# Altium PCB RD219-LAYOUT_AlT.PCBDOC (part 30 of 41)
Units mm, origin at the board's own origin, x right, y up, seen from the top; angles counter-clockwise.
Board outline 209.75 x 159.97 mm, 2 copper layers (TOP, BOTTOM), stack 0 mm thick; 398 components, 199 nets, 1469 pads, 0 vias.
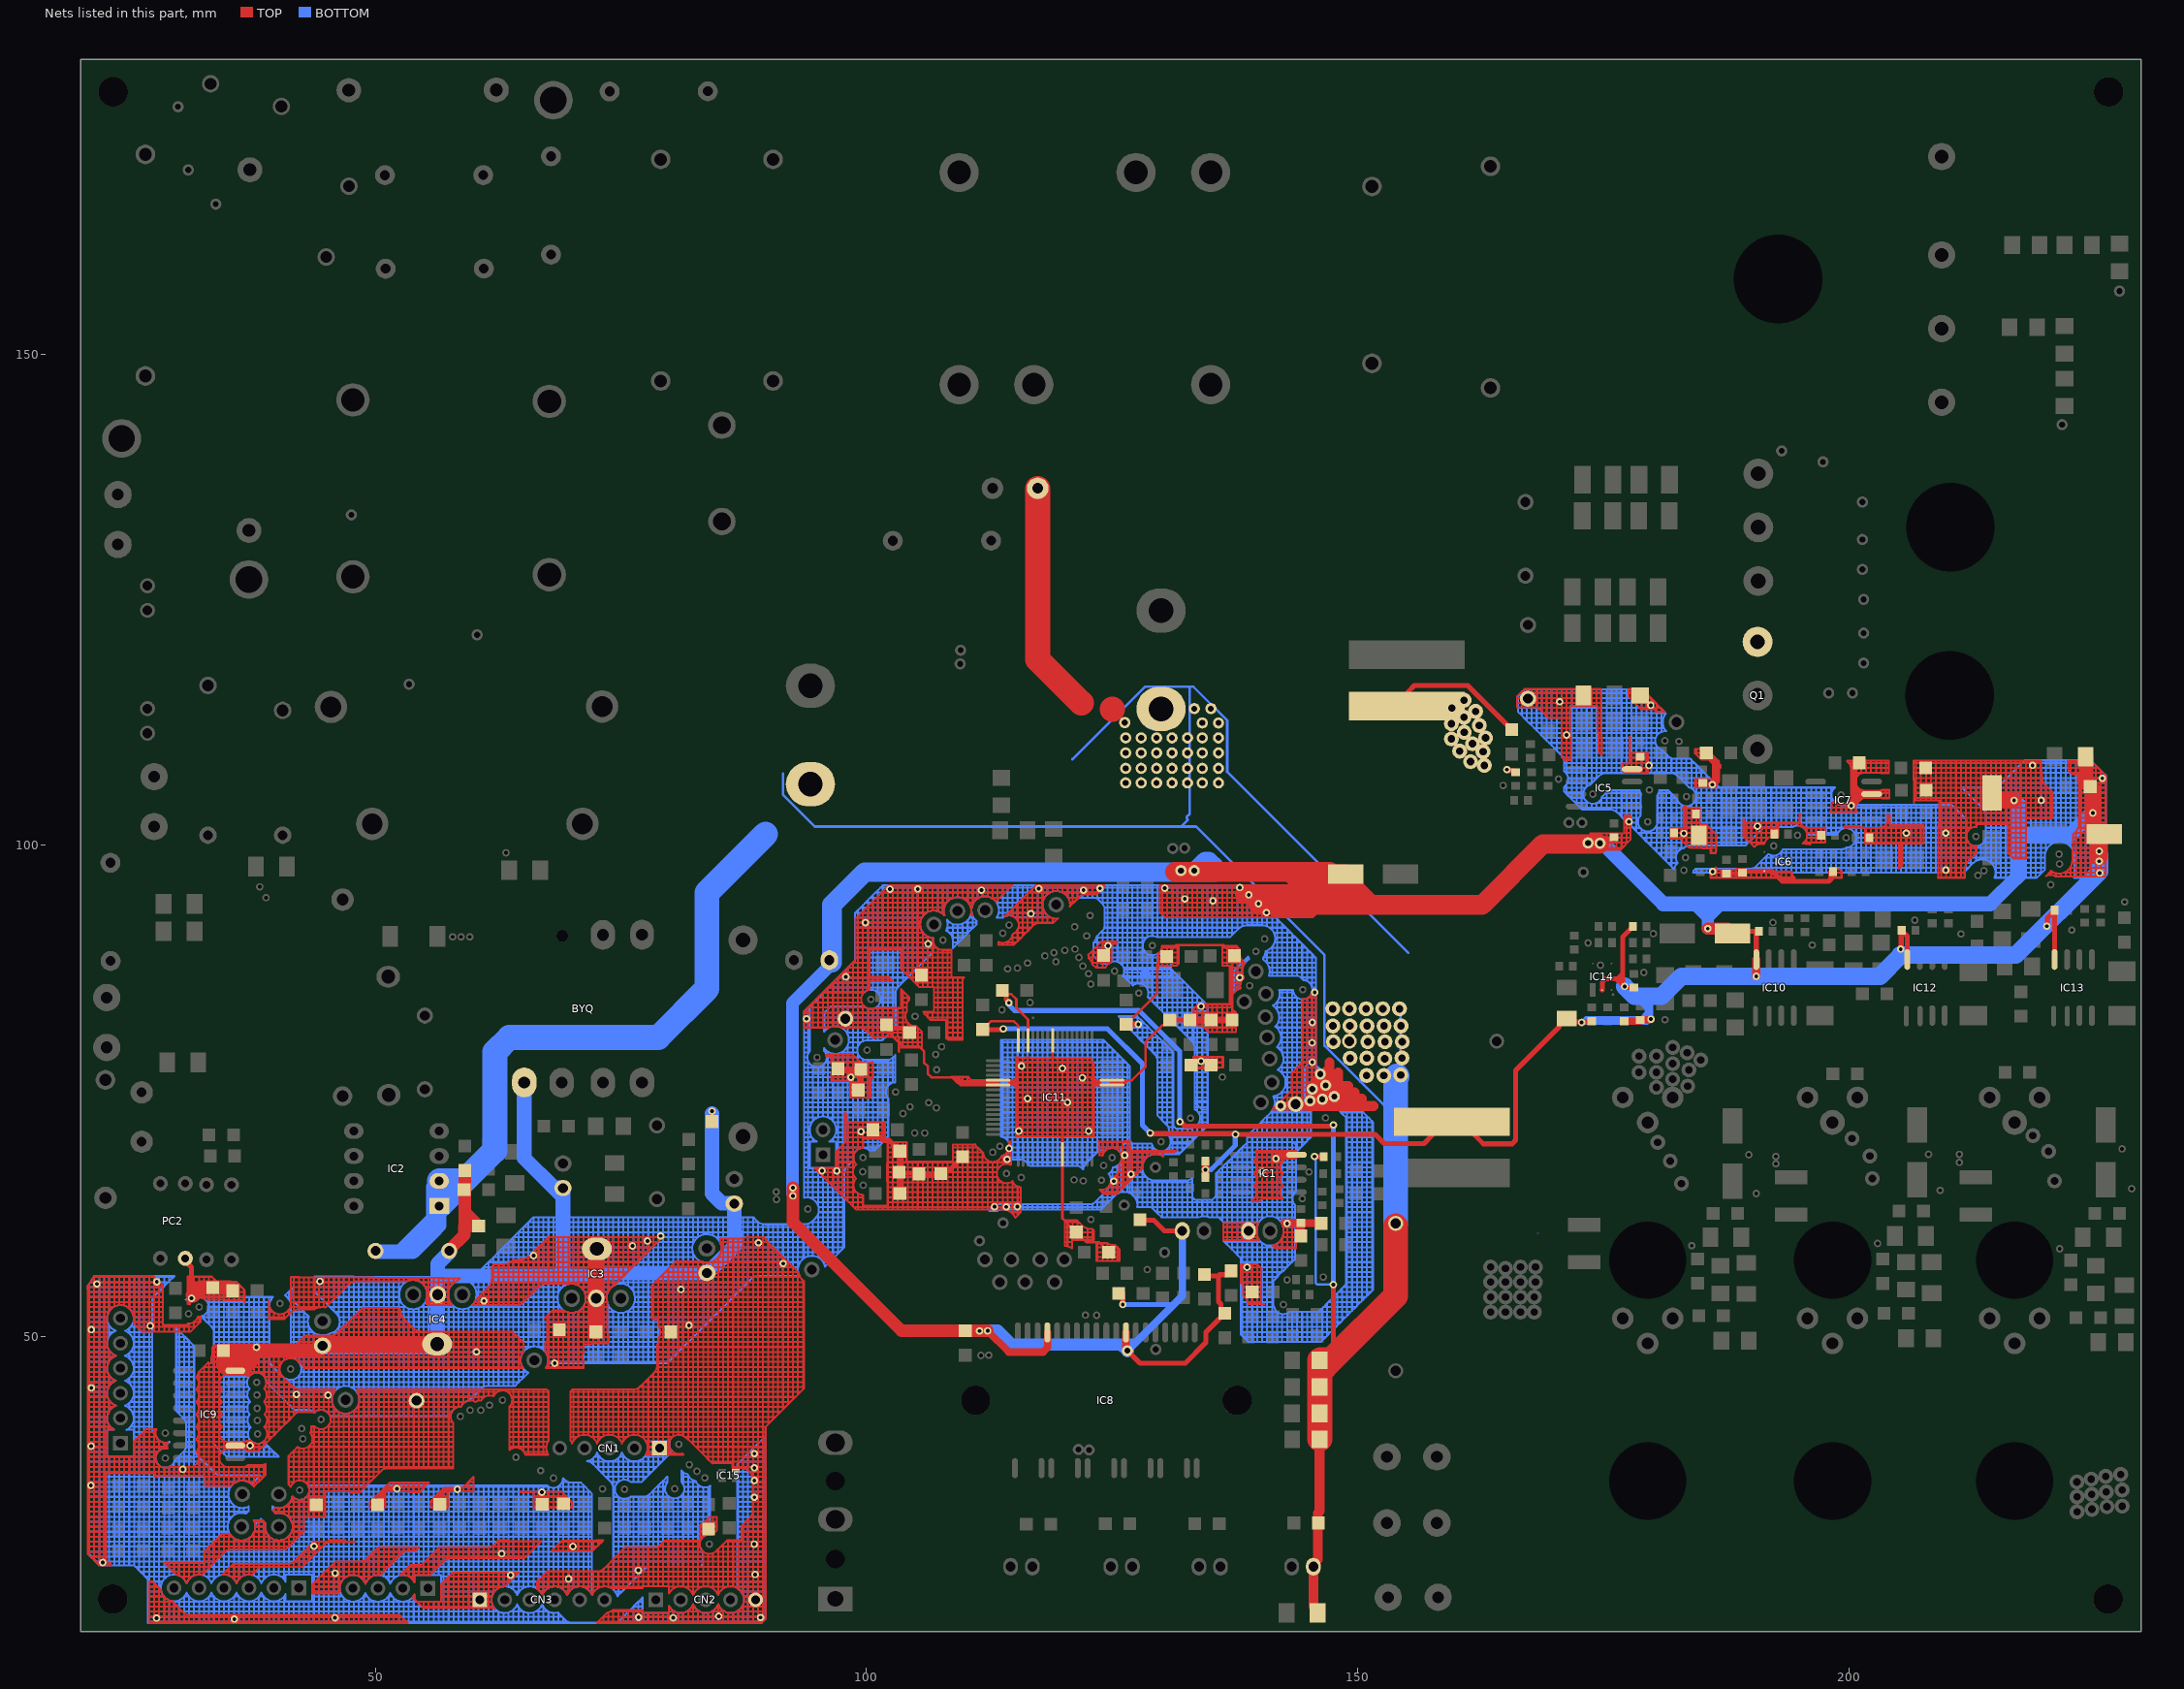
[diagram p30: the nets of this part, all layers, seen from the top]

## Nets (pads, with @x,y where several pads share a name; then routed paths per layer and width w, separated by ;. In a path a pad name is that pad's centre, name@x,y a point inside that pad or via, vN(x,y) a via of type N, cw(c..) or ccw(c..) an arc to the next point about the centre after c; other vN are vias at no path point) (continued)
GND: (continued)
  BOTTOM w0.203: 98.613,86.548 99.121,86.548 ; 98.613,87.056 98.613,87.564 ; 98.613,87.056 99.121,87.056 ; 98.613,87.564 98.613,88.072 ; 98.613,87.564 99.121,87.564 ; 98.613,88.072 98.81,88.269 98.81,88.58 ; 98.613,88.072 99.121,88.072 ; 98.81,88.58 98.81,89.088 ; 98.81,88.58 99.121,88.58 ; 98.81,89.088 98.81,89.596 ; 98.81,89.088 99.121,89.088 ; 98.81,89.596 99.121,89.596 ; 98.81,89.596 98.81,90.104 ; 98.81,90.104 99.121,90.104 ; 98.81,90.104 98.81,90.612 ; 98.81,90.612 99.121,90.612 ; 98.81,90.612 98.81,91.12 ; 98.81,91.12 99.121,91.12 ; 98.81,91.12 98.81,91.628 ; 98.81,91.628 99.121,91.628 ; 98.81,91.628 98.81,92.136 ; 98.81,92.136 99.121,92.136 ; 98.81,92.136 98.81,92.644 ; 98.81,92.644 99.121,92.644 ; 98.81,92.644 98.81,93.095 99.121,93.406 ; 98.816,68.768 cw(c99.642,68.236) 98.818,68.771 cw(c99.642,68.236) 99.121,69.069 ; 99.078,78.928 ccw(c100.051,79.165) 99.121,78.792 ; 99.078,78.928 cw(c100.051,79.165) 99.086,79.436 ; 99.086,79.436 cw(c100.051,79.165) 99.121,79.538 ; 99.121,69.069 cw(c99.642,68.236) 99.629,69.218 ; 99.121,69.069 99.121,69.276 ; 99.121,69.276 99.629,69.276 ; 99.121,69.276 99.121,69.784 ; 99.121,69.784 99.121,70.292 ; 99.121,69.784 99.629,69.784 ; 99.121,70.292 pad.@99.121,70.8 ; 99.121,70.292 99.629,70.292 ; pad.@99.121,70.8 99.121,71.308 ; pad.@99.121,70.8 pad.@99.629,70.8 ; 99.121,71.308 99.121,71.816 ; 99.121,71.308 99.629,71.308 ; 99.121,71.816 99.121,72.324 ; 99.121,71.816 99.629,71.816 ; 99.121,72.324 99.121,72.832 ; 99.121,72.324 99.629,72.324 ; 99.121,72.832 99.121,73.34 ; 99.121,72.832 99.629,72.832 ; 99.121,73.34 99.121,73.848 ; 99.121,73.34 99.629,73.34 ; 99.121,73.848 99.121,74.356 ; 99.121,73.848 99.629,73.848 ; 99.121,74.356 99.121,74.864 ; 99.121,74.356 99.629,74.356 ; 99.121,74.864 99.121,75.372 ; 99.121,74.864 99.629,74.864 ; 99.121,75.372 99.121,75.88 ; 99.121,75.372 99.629,75.372 ; 99.121,75.88 99.121,76.388 ; 99.121,75.88 99.629,75.88 ; 99.121,76.388 99.121,76.896 ; 99.121,76.388 99.629,76.388 ; 99.121,76.896 99.121,77.404 ; 99.121,76.896 99.629,76.896 ; 99.121,77.404 99.121,77.912 ; 99.121,77.404 99.629,77.404 ; 99.121,77.912 99.121,78.42 ; 99.121,77.912 99.629,77.912 ; 99.121,78.42 99.381,78.42 ; 99.121,78.42 99.121,78.792 ; 99.121,78.792 ccw(c100.051,79.165) 99.122,78.79 ccw(c100.051,79.165) 99.381,78.42 ; 99.121,79.538 cw(c100.051,79.165) 99.122,79.54 cw(c100.051,79.165) 99.42,79.944 ; 99.121,79.538 99.121,79.944 ; 99.121,79.944 99.121,80.452 ; 99.121,79.944 99.421,79.944 ; 99.121,80.452 99.121,80.96 ; 99.121,80.452 99.629,80.452 ; 99.121,80.96 99.121,81.468 ; 99.121,80.96 99.629,80.96 ; 99.121,81.468 99.629,81.468 ; 99.121,81.468 99.121,81.976 ; 99.121,81.976 99.121,82.484 ; 99.121,81.976 99.629,81.976 ; 99.121,82.484 99.121,82.992 ; 99.121,82.484 99.629,82.484 ; 99.121,82.992 99.629,82.992 ; 99.121,82.992 99.121,83.5 ; 99.121,83.5 99.629,83.5 ; 99.121,83.5 99.121,83.605 ; 99.121,83.605 99.629,83.605 ; 99.121,85.062 99.629,85.062 ; 99.121,85.062 99.121,85.532 ; 99.121,85.532 99.629,85.532 ; 99.121,85.532 99.121,86.04 ; 99.121,86.04 99.121,86.548 ; 99.121,86.04 99.629,86.04 ; 99.121,86.548 99.121,87.056 ; 99.121,86.548 99.629,86.548 ; 99.121,87.056 99.121,87.564 ; 99.121,87.056 99.629,87.056 ; 99.121,87.564 99.121,88.072 ; 99.121,87.564 99.629,87.564 ; 99.121,88.072 99.121,88.58 ; 99.121,88.072 99.629,88.072 ; 99.121,88.58 99.121,89.088 ; 99.121,88.58 99.629,88.58 ; 99.121,89.088 99.629,89.088 ; 99.121,89.088 99.121,89.596 ; 99.121,89.596 99.121,90.104 ; 99.121,89.596 99.629,89.596 ; 99.121,90.104 99.121,90.612 ; 99.121,90.104 99.629,90.104 ; 99.121,90.612 99.121,91.12 ; 99.121,90.612 99.629,90.612 ; 99.121,91.12 99.121,91.628 ; 99.121,91.12 99.629,91.12 ; 99.121,91.628 99.121,92.136 ; 99.121,91.628 99.629,91.628 ; 99.121,92.136 99.121,92.644 ; 99.121,92.136 pad.@99.629,92.136 ; 99.121,92.644 99.121,93.152 ; 99.121,92.644 99.629,92.644 ; 99.121,93.152 99.629,93.152 ; 99.121,93.152 99.121,93.406 ; 99.121,93.406 99.375,93.66 ; 99.375,93.66 99.629,93.914 ; 99.375,93.66 99.629,93.66 ; 99.381,78.42 ccw(c100.051,79.165) 99.627,78.257 ccw(c100.051,79.165) 99.629,78.257 ; 99.421,79.944 cw(c100.051,79.165) 99.629,80.074 ; 99.629,69.218 cw(c99.642,68.236) 99.642,69.219 cw(c99.642,68.236) 100.137,69.085 ; 99.629,69.218 99.629,69.276 ; 99.629,69.276 99.629,69.784 ; 99.629,69.276 100.137,69.276 ; 99.629,69.784 100.137,69.784 ; 99.629,69.784 99.629,70.292 ; 99.629,70.292 100.137,70.292 ; 99.629,70.292 pad.@99.629,70.8 ; pad.@99.629,70.8 100.137,70.8 ; pad.@99.629,70.8 99.629,71.308 ; 99.629,71.308 99.629,71.816 ; 99.629,71.308 100.137,71.308 ; 99.629,71.816 99.629,72.324 ; 99.629,71.816 100.137,71.816 ; 99.629,72.324 100.137,72.324 ; 99.629,72.324 99.629,72.832 ; 99.629,72.832 99.629,73.34 ; 99.629,72.832 100.137,72.832 ; 99.629,73.34 99.629,73.848 ; 99.629,73.34 100.137,73.34 ; 99.629,73.848 99.629,74.356 ; 99.629,73.848 100.137,73.848 ; 99.629,74.356 100.137,74.356 ; 99.629,74.356 99.629,74.864 ; 99.629,74.864 99.629,75.372 ; 99.629,74.864 100.137,74.864 ; 99.629,75.372 100.137,75.372 ; 99.629,75.372 99.629,75.88 ; 99.629,75.88 100.137,75.88 ; 99.629,75.88 99.629,76.388 ; 99.629,76.388 99.629,76.896 ; 99.629,76.388 100.137,76.388 ; 99.629,76.896 99.629,77.404 ; 99.629,76.896 100.137,76.896 ; 99.629,77.404 99.629,77.912 ; 99.629,77.404 100.137,77.404 ; 99.629,77.912 100.137,77.912 ; 99.629,77.912 99.629,78.257 ; 99.629,78.257 ccw(c100.051,79.165) 100.051,78.164 100.137,78.164 ; 99.629,80.074 cw(c100.051,79.165) 100.051,80.167 100.137,80.167 ; 99.629,80.074 99.629,80.452 ; 99.629,80.452 99.629,80.96 ; 99.629,80.452 100.137,80.452 ; 99.629,80.96 99.629,81.468 ; 99.629,80.96 100.137,80.96 ; 99.629,81.468 100.137,81.468 ; 99.629,81.468 99.629,81.976 ; 99.629,81.976 99.629,82.484 ; 99.629,81.976 100.137,81.976 ; 99.629,82.484 99.629,82.992 ; 99.629,82.484 100.137,82.484 ; 99.629,82.992 99.629,83.5 ; 99.629,82.992 100.137,82.992 ; 99.629,83.5 99.629,83.605 ; 99.629,83.5 99.924,83.5 ; 99.629,85.062 99.629,85.532 ; 99.629,85.532 100.137,85.532 ; 99.629,85.532 99.629,86.04 ; 99.629,86.04 99.629,86.548 ; 99.629,86.04 100.137,86.04 ; 99.629,86.548 99.629,87.056 ; 99.629,86.548 100.137,86.548 ; 99.629,87.056 99.629,87.564 ; 99.629,87.056 100.137,87.056 ; 99.629,87.564 99.629,88.072 ; 99.629,87.564 100.137,87.564 ; 99.629,88.072 99.629,88.58 ; 99.629,88.072 100.137,88.072 ; 99.629,88.58 99.629,89.088 ; 99.629,88.58 100.137,88.58 ; 99.629,89.088 100.137,89.088 ; 99.629,89.088 99.629,89.596 ; 99.629,89.596 99.629,90.104 ; 99.629,89.596 100.137,89.596 ; 99.629,90.104 99.629,90.612 ; 99.629,90.104 100.137,90.104 ; 99.629,90.612 99.629,91.12 ; 99.629,90.612 100.137,90.612 ; 99.629,91.12 99.629,91.628 ; 99.629,91.12 100.137,91.12 ; 99.629,91.628 100.137,91.628 ; 99.629,91.628 pad.@99.629,92.136 ; pad.@99.629,92.136 pad.@99.883,92.136 pad.@100.137,92.136 ; pad.@99.629,92.136 99.629,92.644 ; 99.629,92.644 99.629,93.152 ; 99.629,92.644 100.137,92.644 ; 99.629,93.152 100.137,93.152 ; 99.629,93.152 99.629,93.66 ; 99.629,93.66 99.629,93.914 ; 99.629,93.66 100.137,93.66 ; 99.629,93.914 99.883,94.168 ; 99.883,94.168 100.137,94.168 ; 99.883,94.168 100.137,94.422 ; 99.924,83.5 ccw(c100.444,84.334) 100.137,83.4 ; 100.137,69.085 100.137,69.276 ; 100.137,69.276 100.137,69.784 ; 100.137,69.276 100.645,69.276 ; 100.137,69.784 100.645,69.784 ; 100.137,69.784 100.137,70.292 ; 100.137,70.292 100.645,70.292 ; 100.137,70.292 100.137,70.8 ; 100.137,70.8 100.137,71.308 ; 100.137,70.8 100.645,70.8 ; 100.137,71.308 100.137,71.816 ; 100.137,71.308 100.645,71.308 ; 100.137,71.816 100.137,72.324 ; 100.137,71.816 100.645,71.816 ; 100.137,72.324 100.645,72.324 ; 100.137,72.324 100.137,72.832 ; 100.137,72.832 100.137,73.34 ; 100.137,72.832 100.645,72.832 ; 100.137,73.34 100.137,73.848 ; 100.137,73.34 100.645,73.34 ; 100.137,73.848 100.137,74.356 ; 100.137,73.848 100.645,73.848 ; 100.137,74.356 100.645,74.356 ; 100.137,74.356 100.137,74.864 ; 100.137,74.864 100.137,75.372 ; 100.137,74.864 100.645,74.864 ; 100.137,75.372 100.645,75.372 ; 100.137,75.372 100.137,75.88 ; 100.137,75.88 100.645,75.88 ; 100.137,75.88 100.137,76.388 ; 100.137,76.388 100.137,76.896 ; 100.137,76.388 100.645,76.388 ; 100.137,76.896 100.137,77.404 ; 100.137,76.896 100.645,76.896 ; 100.137,77.404 100.137,77.912 ; 100.137,77.404 100.645,77.404 ; 100.137,77.912 100.137,78.164 ; 100.137,77.912 100.645,77.912 ; 100.137,78.164 100.645,78.164 ; 100.137,80.167 100.645,80.167 ; 100.137,80.167 100.137,80.452 ; 100.137,80.452 100.137,80.96 ; 100.137,80.452 100.645,80.452 ; 100.137,80.96 100.137,81.468 ; 100.137,80.96 100.645,80.96 ; 100.137,81.468 100.645,81.468 ; 100.137,81.468 100.137,81.976 ; 100.137,81.976 100.137,82.484 ; 100.137,81.976 100.645,81.976 ; 100.137,82.484 100.137,82.992 ; 100.137,82.484 100.645,82.484 ; 100.137,82.992 100.645,82.992 ; 100.137,82.992 100.137,83.4 ; 100.137,83.4 ccw(c100.444,84.334) 100.645,83.372 ; 100.137,85.267 cw(c100.444,84.334) 100.14,85.268 cw(c100.444,84.334) 100.645,85.296 ; 100.137,85.267 100.137,85.532 ; 100.137,85.532 100.137,86.04 ; 100.137,85.532 100.645,85.532 ; 100.137,86.04 100.137,86.548 ; 100.137,86.04 100.645,86.04 ; 100.137,86.548 100.137,87.056 ; 100.137,86.548 100.645,86.548 ; 100.137,87.056 100.137,87.564 ; 100.137,87.056 100.645,87.056 ; 100.137,87.564 100.137,88.072 ; 100.137,87.564 100.645,87.564 ; 100.137,88.072 100.137,88.58 ; 100.137,88.072 100.645,88.072 ; 100.137,88.58 100.137,89.088 ; 100.137,88.58 100.645,88.58 ; 100.137,89.088 100.137,89.596 ; 100.137,89.088 100.645,89.088 ; 100.137,89.596 100.137,90.104 ; 100.137,89.596 100.645,89.596 ; 100.137,90.104 100.137,90.612 ; 100.137,90.104 100.645,90.104 ; 100.137,90.612 100.137,91.12 ; 100.137,90.612 100.645,90.612 ; 100.137,91.12 100.137,91.628 ; 100.137,91.12 100.645,91.12 ; 100.137,91.628 100.645,91.628 ; 100.137,91.628 pad.@100.137,92.136 ; pad.@100.137,92.136 100.645,92.136 ; pad.@100.137,92.136 100.137,92.644 ; 100.137,92.644 100.137,93.152 ; 100.137,92.644 100.645,92.644 ; 100.137,93.152 100.137,93.66 ; 100.137,93.152 100.645,93.152 ; 100.137,93.66 100.137,94.168 ; 100.137,93.66 100.645,93.66 ; 100.137,94.168 100.137,94.422 ; 100.137,94.168 100.645,94.168 ; 100.137,94.422 100.391,94.676 ; 100.391,94.676 100.645,94.676 ; 100.391,94.676 100.645,94.93 ; 100.645,68.965 100.827,68.965 101.139,69.276 ; 100.645,68.965 100.645,69.276 ; 100.645,69.276 100.645,69.784 ; 100.645,69.276 101.139,69.276 ; 100.645,69.784 101.153,69.784 ; 100.645,69.784 100.645,70.292 ; 100.645,70.292 100.645,70.8 ; 100.645,70.292 101.153,70.292 ; 100.645,70.8 100.645,71.308 ; 100.645,70.8 101.153,70.8 ; 100.645,71.308 100.645,71.816 ; 100.645,71.308 101.153,71.308 ; 100.645,71.816 100.645,72.324 ; 100.645,71.816 101.153,71.816 ; 100.645,72.324 101.153,72.324 ; 100.645,72.324 100.645,72.832 ; 100.645,72.832 100.645,73.34 ; 100.645,72.832 101.153,72.832 ; 100.645,73.34 100.645,73.848 ; 100.645,73.34 101.153,73.34 ; 100.645,73.848 100.645,74.356 ; 100.645,73.848 101.153,73.848 ; 100.645,74.356 100.645,74.864 ; 100.645,74.356 101.153,74.356 ; 100.645,74.864 100.645,75.372 ; 100.645,74.864 101.153,74.864 ; 100.645,75.372 100.645,75.88 ; 100.645,75.372 101.153,75.372 ; 100.645,75.88 100.645,76.388 ; 100.645,75.88 101.153,75.88 ; 100.645,76.388 100.645,76.896 ; 100.645,76.388 101.153,76.388 ; 100.645,76.896 100.645,77.404 ; 100.645,76.896 101.153,76.896 ; 100.645,77.404 100.645,77.912 ; 100.645,77.404 101.153,77.404 ; 100.645,77.912 100.645,78.164 ; 100.645,77.912 101.153,77.912 ; 100.645,78.164 101.153,78.164 ; 100.645,80.167 100.645,80.452 ; 100.645,80.167 101.153,80.167 ; 100.645,80.452 100.645,80.96 ; 100.645,80.452 101.153,80.452 ; 100.645,80.96 100.645,81.468 ; 100.645,80.96 101.153,80.96 ; 100.645,81.468 100.645,81.976 ; 100.645,81.468 101.153,81.468 ; 100.645,81.976 100.645,82.484 ; 100.645,81.976 101.153,81.976 ; 100.645,82.484 100.645,82.992 ; 100.645,82.484 101.153,82.484 ; 100.645,82.992 101.153,82.992 ; 100.645,82.992 100.645,83.372 ; 100.645,83.372 ccw(c100.444,84.334) 100.648,83.373 ccw(c100.444,84.334) 100.963,83.5 101.153,83.5 ; 100.645,85.296 cw(c100.444,84.334) 100.648,85.295 cw(c100.444,84.334) 101.143,85.024 ; 100.645,85.296 100.645,85.532 ; 100.645,85.532 101.153,85.532 ; 100.645,85.532 100.645,86.04 ; 100.645,86.04 100.645,86.548 ; 100.645,86.04 101.153,86.04 ; 100.645,86.548 100.645,87.056 ; 100.645,86.548 101.153,86.548 ; 100.645,87.056 100.645,87.564 ; 100.645,87.056 101.153,87.056 ; 100.645,87.564 100.645,88.072 ; 100.645,87.564 101.153,87.564 ; 100.645,88.072 100.645,88.58 ; 100.645,88.072 101.153,88.072 ; 100.645,88.58 100.645,89.088 ; 100.645,88.58 101.153,88.58 ; 100.645,89.088 101.153,89.088 ; 100.645,89.088 100.645,89.596 ; 100.645,89.596 100.645,90.104 ; 100.645,89.596 101.153,89.596 ; 100.645,90.104 100.645,90.612 ; 100.645,90.104 101.153,90.104 ; 100.645,90.612 100.645,91.12 ; 100.645,90.612 101.153,90.612 ; 100.645,91.12 100.645,91.628 ; 100.645,91.12 101.153,91.12 ; 100.645,91.628 100.645,92.136 ; 100.645,91.628 101.153,91.628 ; 100.645,92.136 100.645,92.644 ; 100.645,92.136 101.153,92.136 ; 100.645,92.644 100.645,93.152 ; 100.645,92.644 101.153,92.644 ; 100.645,93.152 101.153,93.152 ; 100.645,93.152 100.645,93.66 ; 100.645,93.66 100.645,94.168 ; 100.645,93.66 101.153,93.66 ; 100.645,94.168 100.645,94.676 ; 100.645,94.168 101.153,94.168 ; 100.645,94.676 100.645,94.93 ; 100.645,94.676 101.153,94.676 ; 100.645,94.93 100.899,95.184 ; 100.899,95.184 101.153,95.438 ; 100.899,95.184 101.153,95.184 ; 101.139,69.276 101.153,69.29 ; 101.143,85.024 cw(c100.444,84.334) 101.153,85.014 ; 101.143,85.024 101.153,85.024 ; 101.153,69.29 101.647,69.784 ; 101.153,69.29 101.153,69.784 ; 101.153,69.784 101.153,70.292 ; 101.153,69.784 101.647,69.784 ; 101.153,70.292 101.661,70.292 ; 101.153,70.292 101.153,70.8 ; 101.153,70.8 101.153,71.308 ; 101.153,70.8 101.661,70.8 ; 101.153,71.308 101.153,71.816 ; 101.153,71.308 101.661,71.308 ; 101.153,71.816 101.153,72.324 ; 101.153,71.816 101.661,71.816 ; 101.153,72.324 101.661,72.324 ; 101.153,72.324 101.153,72.832 ; 101.153,72.832 101.153,73.34 ; 101.153,72.832 101.661,72.832 ; 101.153,73.34 101.153,73.848 ; 101.153,73.34 101.661,73.34 ; 101.153,73.848 101.153,74.356 ; 101.153,73.848 101.661,73.848 ; 101.153,74.356 101.661,74.356 ; 101.153,74.356 101.153,74.864 ; 101.153,74.864 101.153,75.372 ; 101.153,74.864 101.661,74.864 ; 101.153,75.372 101.661,75.372 ; 101.153,75.372 101.153,75.88 ; 101.153,75.88 101.661,75.88 ; 101.153,75.88 101.153,76.388 ; 101.153,76.388 101.153,76.896 ; 101.153,76.388 101.661,76.388 ; 101.153,76.896 101.153,77.404 ; 101.153,76.896 101.661,76.896 ; 101.153,77.404 101.153,77.912 ; 101.153,77.404 101.661,77.404 ; 101.153,77.912 101.153,78.164 ; 101.153,77.912 101.661,77.912 ; 101.153,78.164 101.661,78.164 ; 101.153,80.167 101.153,80.452 ; 101.153,80.167 101.61,80.167 101.661,80.217 ; 101.153,80.452 101.153,80.96 ; 101.153,80.452 101.661,80.452 ; 101.153,80.96 101.153,81.468 ; 101.153,80.96 101.661,80.96 ; 101.153,81.468 101.661,81.468 ; 101.153,81.468 101.153,81.976 ; 101.153,81.976 101.153,82.484 ; 101.153,81.976 101.661,81.976 ; 101.153,82.484 101.153,82.992 ; 101.153,82.484 101.661,82.484 ; 101.153,82.992 101.661,82.992 ; 101.153,82.992 101.153,83.5 ; 101.153,83.5 101.661,83.5 ; 101.153,83.5 101.153,83.654 ; 101.153,85.014 cw(c100.444,84.334) 101.409,84.516 ; 101.153,85.014 101.153,85.024 ; 101.153,85.024 101.661,85.024 ; 101.153,85.024 101.153,85.532 ; 101.153,85.532 101.661,85.532 ; 101.153,85.532 101.153,86.04 ; 101.153,86.04 101.153,86.548 ; 101.153,86.04 101.661,86.04 ; 101.153,86.548 101.153,87.056 ; 101.153,86.548 101.661,86.548 ; 101.153,87.056 101.153,87.564 ; 101.153,87.056 101.661,87.056 ; 101.153,87.564 101.153,88.072 ; 101.153,87.564 101.661,87.564 ; 101.153,88.072 101.153,88.58 ; 101.153,88.072 101.661,88.072 ; 101.153,88.58 101.153,89.088 ; 101.153,88.58 101.661,88.58 ; 101.153,89.088 101.661,89.088 ; 101.153,89.088 101.153,89.596 ; 101.153,89.596 101.153,90.104 ; 101.153,89.596 101.661,89.596 ; 101.153,90.104 101.153,90.612 ; 101.153,90.104 101.661,90.104 ; 101.153,90.612 101.153,91.12 ; 101.153,90.612 101.661,90.612 ; 101.153,91.12 101.153,91.628 ; 101.153,91.12 101.661,91.12 ; 101.153,91.628 101.153,92.136 ; 101.153,91.628 101.661,91.628 ; 101.153,92.136 101.153,92.644 ; 101.153,92.136 101.661,92.136 ; 101.153,92.644 101.153,93.152 ; 101.153,92.644 101.661,92.644 ; 101.153,93.152 101.153,93.66 ; 101.153,93.152 101.661,93.152 ; 101.153,93.66 101.153,94.168 ; 101.153,93.66 101.661,93.66 ; 101.153,94.168 101.153,94.676 ; 101.153,94.168 101.661,94.168 ; 101.153,94.676 101.153,95.184 ; 101.153,94.676 101.661,94.676 ; 101.153,95.184 101.153,95.438 ; 101.153,95.184 101.661,95.184 ; 101.153,95.438 101.407,95.692 ; 101.407,95.692 101.661,95.946 ; 101.407,95.692 101.661,95.692 ; 101.409,84.516 101.661,84.516 ; 101.647,69.784 101.661,69.798 ; 101.661,69.798 102.155,70.292 ; 101.661,69.798 101.661,70.292 ; 101.661,70.292 102.155,70.292 ; 101.661,70.292 101.661,70.8 ; 101.661,70.8 101.661,71.308 ; 101.661,70.8 102.169,70.8 ; 101.661,71.308 101.661,71.816 ; 101.661,71.308 102.169,71.308 ; 101.661,71.816 101.661,72.324 ; 101.661,71.816 102.169,71.816 ; 101.661,72.324 102.169,72.324 ; 101.661,72.324 101.661,72.832 ; 101.661,72.832 101.661,73.34 ; 101.661,72.832 102.169,72.832 ; 101.661,73.34 101.661,73.848 ; 101.661,73.34 102.169,73.34 ; 101.661,73.848 101.661,74.356 ; 101.661,73.848 102.169,73.848 ; 101.661,74.356 101.661,74.864 ; 101.661,74.356 102.139,74.356 ; 101.661,74.864 101.661,75.372 ; 101.661,74.864 101.971,74.864 ; 101.661,75.372 101.661,75.88 ; 101.661,75.372 102.087,75.372 ; 101.661,75.88 102.169,75.88 ; 101.661,75.88 101.661,76.388 ; 101.661,76.388 101.661,76.896 ; 101.661,76.388 102.169,76.388 ; 101.661,76.896 101.661,77.404 ; 101.661,76.896 102.169,76.896 ; 101.661,77.404 101.661,77.912 ; 101.661,77.404 102.169,77.404 ; 101.661,77.912 101.661,78.164 ; 101.661,77.912 102.169,77.912 ; 101.661,78.164 102.025,78.164 ; 101.661,80.217 101.661,80.452 ; 101.661,80.217 101.896,80.452 ; 101.661,80.452 101.661,80.96 ; 101.661,80.452 101.896,80.452 ; 101.661,80.96 101.661,81.468 ; 101.661,80.96 102.169,80.96 ; 101.661,81.468 102.169,81.468 ; 101.661,81.468 101.661,81.976 ; 101.661,81.976 101.661,82.484 ; 101.661,81.976 102.169,81.976 ; 101.661,82.484 101.661,82.992 ; 101.661,82.484 102.169,82.484 ; 101.661,82.992 101.661,83.5 ; 101.661,82.992 102.169,82.992 ; 101.661,83.5 101.661,84.008 ; 101.661,83.5 102.169,83.5 ; 101.661,84.008 101.661,84.516 ; 101.661,84.008 102.169,84.008 ; 101.661,84.516 102.169,84.516 ; 101.661,84.516 101.661,85.024 ; 101.661,85.024 102.169,85.024 ; 101.661,85.024 101.661,85.532 ; 101.661,85.532 102.169,85.532 ; 101.661,85.532 101.661,86.04 ; 101.661,86.04 101.661,86.548 ; 101.661,86.04 102.169,86.04 ; 101.661,86.548 101.661,87.056 ; 101.661,86.548 102.169,86.548 ; 101.661,87.056 101.661,87.564 ; 101.661,87.056 102.169,87.056 ; 101.661,87.564 101.661,88.072 ; 101.661,87.564 102.169,87.564 ; 101.661,88.072 101.661,88.58 ; 101.661,88.072 102.169,88.072 ; 101.661,88.58 101.661,89.088 ; 101.661,88.58 102.169,88.58 ; 101.661,89.088 102.169,89.088 ; 101.661,89.088 101.661,89.596 ; 101.661,89.596 101.661,90.104 ; 101.661,89.596 102.169,89.596 ; 101.661,90.104 101.661,90.612 ; 101.661,90.104 102.169,90.104 ; 101.661,90.612 101.661,91.12 ; 101.661,90.612 102.169,90.612 ; 101.661,91.12 101.661,91.628 ; 101.661,91.12 102.169,91.12 ; 101.661,91.628 101.661,92.136 ; 101.661,91.628 102.169,91.628 ; 101.661,92.136 101.661,92.644 ; 101.661,92.136 102.169,92.136 ; 101.661,92.644 101.661,93.152 ; 101.661,92.644 102.169,92.644 ; 101.661,93.152 102.169,93.152 ; 101.661,93.152 101.661,93.66 ; 101.661,93.66 101.661,94.168 ; 101.661,93.66 102.169,93.66 ; 101.661,94.168 101.661,94.676 ; 101.661,94.168 102.169,94.168 ; 101.661,94.676 101.661,95.184 ; 101.661,94.676 102.169,94.676 ; 101.661,95.184 101.661,95.692 ; 101.661,95.184 102.169,95.184 ; 101.661,95.692 101.661,95.946 ; 101.661,95.692 pad.@102.169,95.692 ; 101.661,95.946 102.169,95.946 ; 101.896,80.452 102.169,80.725 ; 101.971,74.864 ccw(c102.953,74.907) 102.139,74.356 ; 101.971,74.864 cw(c102.953,74.907) 102.087,75.372 ; 102.025,78.164 ccw(c102.025,79.165) 102.169,78.174 ; 102.025,78.164 ccw(c102.025,79.165) 102.169,78.174 ; 102.087,75.372 cw(c102.953,74.907) 102.169,75.499 ; 102.139,74.356 ccw(c102.953,74.907) 102.169,74.314 ; 102.155,70.292 102.169,70.306 ; 102.169,70.306 102.169,70.8 ; 102.169,70.306 102.224,70.362 102.224,70.8 ; 102.169,70.8 102.169,71.308 ; 102.169,70.8 102.224,70.8 ; 102.169,71.308 102.169,71.816 ; 102.169,71.308 102.224,71.308 ; 102.169,71.816 102.169,72.324 ; 102.169,71.816 102.224,71.816 ; 102.169,72.324 102.169,72.832 ; 102.169,72.324 102.224,72.324 ; 102.169,72.832 102.169,73.34 ; 102.169,72.832 102.224,72.832 ; 102.169,73.34 102.169,73.848 ; 102.169,73.34 102.224,73.34 ; 102.169,73.848 102.224,73.848 ; 102.169,73.848 102.169,74.314 ; 102.169,75.499 cw(c102.953,74.907) 102.677,75.85 ; 102.169,75.499 102.169,75.88 ; 102.169,75.88 102.677,75.88 ; 102.169,75.88 102.169,76.388 ; 102.169,76.388 102.169,76.896 ; 102.169,76.388 102.677,76.388 ; 102.169,76.896 102.169,77.404 ; 102.169,76.896 102.677,76.896 ; 102.169,77.404 102.169,77.912 ; 102.169,77.404 102.677,77.404 ; 102.169,77.912 102.677,77.912 ; 102.169,77.912 102.169,78.174 ; 102.169,78.174 ccw(c102.025,79.165) 102.677,78.405 ; 102.169,78.174 ccw(c102.025,79.165) 102.677,78.405 ; 102.169,80.725 102.169,80.96 ; 102.169,80.725 102.404,80.96 ; 102.169,80.96 102.169,81.468 ; 102.169,80.96 102.404,80.96 ; 102.169,81.468 102.169,81.976 ; 102.169,81.468 102.677,81.468 ; 102.169,81.976 102.169,82.484 ; 102.169,81.976 102.677,81.976 ; 102.169,82.484 102.169,82.992 ; 102.169,82.484 102.677,82.484 ; 102.169,82.992 102.169,83.5 ; 102.169,82.992 102.677,82.992 ; 102.169,83.5 102.169,84.008 ; 102.169,83.5 102.677,83.5 ; 102.169,84.008 102.169,84.516 ; 102.169,84.008 102.677,84.008 ; 102.169,84.516 102.169,85.024 ; 102.169,84.516 102.677,84.516 ; 102.169,85.024 102.169,85.532 ; 102.169,85.024 102.677,85.024 ; 102.169,85.532 102.169,86.04 ; 102.169,85.532 102.677,85.532 ; 102.169,86.04 102.169,86.548 ; 102.169,86.04 102.677,86.04 ; 102.169,86.548 102.169,87.056 ; 102.169,86.548 102.677,86.548 ; 102.169,87.056 102.169,87.564 ; 102.169,87.056 102.677,87.056 ; 102.169,87.564 102.169,88.072 ; 102.169,87.564 102.677,87.564 ; 102.169,88.072 102.169,88.58 ; 102.169,88.072 102.677,88.072 ; 102.169,88.58 102.169,89.088 ; 102.169,88.58 102.677,88.58 ; 102.169,89.088 102.169,89.596 ; 102.169,89.088 102.677,89.088 ; 102.169,89.596 102.169,90.104 ; 102.169,89.596 102.677,89.596 ; 102.169,90.104 102.169,90.612 ; 102.169,90.104 102.677,90.104 ; 102.169,90.612 102.169,91.12 ; 102.169,90.612 102.677,90.612 ; 102.169,91.12 102.169,91.628 ; 102.169,91.12 102.677,91.12 ; 102.169,91.628 102.169,92.136 ; 102.169,91.628 102.677,91.628 ; 102.169,92.136 102.169,92.644 ; 102.169,92.136 102.677,92.136 ; 102.169,92.644 102.169,93.152 ; 102.169,92.644 102.677,92.644 ; 102.169,93.152 102.169,93.66 ; 102.169,93.152 102.677,93.152 ; 102.169,93.66 102.169,94.168 ; 102.169,93.66 102.677,93.66 ; 102.169,94.168 102.169,94.676 ; 102.169,94.168 102.677,94.168 ; 102.169,94.676 102.169,95.184 ; 102.169,94.676 102.677,94.676 ; 102.169,95.184 102.677,95.184 ; 102.169,95.184 pad.@102.169,95.692 ; pad.@102.169,95.692 102.169,95.946 ; pad.@102.169,95.692 pad.@102.677,95.692 ; 102.169,95.946 102.677,95.946 ; 102.224,70.8 102.224,71.308 ; 102.224,71.308 102.224,71.816 ; 102.224,71.816 102.224,72.324 ; 102.224,72.324 102.224,72.832 ; 102.224,72.832 102.224,73.34 ; 102.224,73.34 102.224,73.848 ; 102.404,80.96 102.677,81.233 ; 102.677,75.85 cw(c102.953,74.907) 102.818,75.88 ; 102.677,75.85 102.677,75.88 ; 102.677,75.88 102.677,76.388 ; 102.677,75.88 102.818,75.88 ; 102.677,76.388 102.677,76.896 ; 102.677,76.388 102.941,76.388 ; 102.677,76.896 102.677,77.404 ; 102.677,76.896 102.941,76.896 ; 102.677,77.404 102.677,77.912 ; 102.677,77.404 102.941,77.404 ; 102.677,77.912 102.941,77.912 ; 102.677,77.912 102.677,78.405 ; 102.677,78.405 ccw(c102.025,79.165) 102.694,78.42 ; 102.677,78.405 ccw(c102.025,79.165) 102.694,78.42 ; 102.677,81.233 102.677,81.468 ; 102.677,81.233 102.945,81.502 102.945,81.976 ; 102.677,81.468 102.677,81.976 ; 102.677,81.976 102.677,82.484 ; 102.677,81.976 102.945,81.976 ; 102.677,82.484 102.677,82.992 ; 102.677,82.484 102.945,82.484 ; 102.677,82.992 102.677,83.5 ; 102.677,82.992 102.945,82.992 ; 102.677,83.5 102.677,84.008 ; 102.677,83.5 102.945,83.5 ; 102.677,84.008 102.677,84.516 ; 102.677,84.008 102.945,84.008 ; 102.677,84.516 102.677,85.024 ; 102.677,84.516 102.945,84.516 ; 102.677,85.024 102.677,85.532 ; 102.677,85.024 102.954,85.024 ; 102.677,85.532 102.677,86.04 ; 102.677,85.532 103.172,85.532 ; 102.677,86.04 102.677,86.548 ; 102.677,86.04 103.185,86.04 ; 102.677,86.548 102.677,87.056 ; 102.677,86.548 103.185,86.548 ; 102.677,87.056 102.677,87.564 ; 102.677,87.056 103.185,87.056 ; 102.677,87.564 102.677,88.072 ; 102.677,87.564 103.185,87.564 ; 102.677,88.072 102.677,88.58 ; 102.677,88.072 103.185,88.072 ; 102.677,88.58 102.677,89.088 ; 102.677,88.58 103.185,88.58 ; 102.677,89.088 103.185,89.088 ; 102.677,89.088 102.677,89.596 ; 102.677,89.596 102.677,90.104 ; 102.677,89.596 103.185,89.596 ; 102.677,90.104 102.677,90.612 ; 102.677,90.104 103.185,90.104 ; 102.677,90.612 102.677,91.12 ; 102.677,90.612 103.185,90.612 ; 102.677,91.12 102.677,91.628 ; 102.677,91.12 103.185,91.12 ; 102.677,91.628 102.677,92.136 ; 102.677,91.628 103.185,91.628 ; 102.677,92.136 102.677,92.644 ; 102.677,92.136 103.185,92.136 ; 102.677,92.644 102.677,93.152 ; 102.677,92.644 103.185,92.644 ; 102.677,93.152 103.185,93.152 ; 102.677,93.152 102.677,93.66 ; 102.677,93.66 102.677,94.168 ; 102.677,93.66 103.185,93.66 ; 102.677,94.168 102.677,94.676 ; 102.677,94.168 103.185,94.168 ; 102.677,94.676 102.677,95.184 ; 102.677,94.676 103.185,94.676 ; 102.677,95.184 103.185,95.184 ; 102.677,95.184 pad.@102.677,95.692 ; pad.@102.677,95.692 103.185,95.692 ; pad.@102.677,95.692 102.677,95.946 ; 102.677,95.946 103.185,95.946 ; 102.694,78.42 ccw(c102.025,79.165) 102.733,78.457 cw(c102.025,79.165) 102.694,78.42 ; 102.694,78.42 102.941,78.42 ; 102.941,76.388 102.941,76.896 ; 102.941,76.896 102.941,77.404 ; 102.941,77.404 102.941,77.912 ; 102.941,77.912 102.941,78.42 ; 102.945,81.976 102.945,82.484 ; 102.945,82.484 102.945,82.992 ; 102.945,82.992 102.945,83.5 ; 102.945,83.5 102.945,84.008 ; 102.945,84.008 102.945,84.516 ; 102.945,84.516 102.945,84.897 ; 102.945,84.897 cw(c103.947,84.897) 102.954,85.024 ; 102.945,84.897 cw(c103.947,84.897) 102.954,85.024 ; 102.954,85.024 cw(c103.947,84.897) 103.172,85.532 ; 102.954,85.024 cw(c103.947,84.897) 103.172,85.532 ; 103.172,85.532 cw(c103.947,84.897) 103.185,85.547 ; 103.172,85.532 cw(c103.947,84.897) 103.185,85.547 ; 103.185,85.547 cw(c103.947,84.897) 103.239,85.605 ccw(c103.947,84.897) 103.185,85.547 ; 103.185,85.547 103.185,86.04 ; 103.185,86.04 103.185,86.548 ; 103.185,86.04 103.674,86.04 ; 103.185,86.548 103.185,87.056 ; 103.185,86.548 103.693,86.548 ; 103.185,87.056 103.185,87.564 ; 103.185,87.056 103.693,87.056 ; 103.185,87.564 103.185,88.072 ; 103.185,87.564 103.693,87.564 ; 103.185,88.072 103.185,88.58 ; 103.185,88.072 103.693,88.072 ; 103.185,88.58 103.185,89.088 ; 103.185,88.58 103.693,88.58 ; 103.185,89.088 103.185,89.596 ; 103.185,89.088 103.693,89.088 ; 103.185,89.596 103.185,90.104 ; 103.185,89.596 103.693,89.596 ; 103.185,90.104 103.185,90.612 ; 103.185,90.104 103.693,90.104 ; 103.185,90.612 103.185,91.12 ; 103.185,90.612 103.693,90.612 ; 103.185,91.12 103.185,91.628 ; 103.185,91.12 103.693,91.12 ; 103.185,91.628 103.185,92.136 ; 103.185,91.628 103.693,91.628 ; 103.185,92.136 103.185,92.644 ; 103.185,92.136 103.693,92.136 ; 103.185,92.644 103.185,93.152 ; 103.185,92.644 103.693,92.644 ; 103.185,93.152 103.693,93.152 ; 103.185,93.152 103.185,93.66 ; 103.185,93.66 103.185,94.168 ; 103.185,93.66 103.693,93.66 ; 103.185,94.168 103.185,94.676 ; 103.185,94.168 103.693,94.168 ; 103.185,94.676 103.185,95.184 ; 103.185,94.676 103.693,94.676 ; 103.185,95.184 103.185,95.692 ; 103.185,95.184 103.693,95.184 ; 103.185,95.692 103.693,95.692 ; 103.185,95.692 103.185,95.946 ; 103.185,95.946 103.693,95.946 ; 103.674,86.04 103.693,86.059 ; 103.693,86.059 104.182,86.548 ; 103.693,86.059 103.693,86.548 ; 103.693,86.548 103.693,87.056 ; 103.693,86.548 104.182,86.548 ; 103.693,87.056 103.693,87.564 ; 103.693,87.056 104.201,87.056 ; 103.693,87.564 103.693,88.072 ; 103.693,87.564 104.201,87.564 ; 103.693,88.072 103.693,88.58 ; 103.693,88.072 104.201,88.072 ; 103.693,88.58 103.693,89.088 ; 103.693,88.58 104.201,88.58 ; 103.693,89.088 103.693,89.596 ; 103.693,89.088 104.201,89.088 ; 103.693,89.596 103.693,90.104 ; 103.693,89.596 104.201,89.596 ; 103.693,90.104 103.693,90.612 ; 103.693,90.104 104.201,90.104 ; 103.693,90.612 103.693,91.12 ; 103.693,90.612 104.201,90.612 ; 103.693,91.12 103.693,91.628 ; 103.693,91.12 104.201,91.12 ; 103.693,91.628 103.693,92.136 ; 103.693,91.628 104.201,91.628 ; 103.693,92.136 103.693,92.644 ; 103.693,92.136 104.201,92.136 ; 103.693,92.644 103.693,93.152 ; 103.693,92.644 104.201,92.644 ; 103.693,93.152 103.693,93.66 ; 103.693,93.152 104.201,93.152 ; 103.693,93.66 103.693,94.168 ; 103.693,93.66 104.201,93.66 ; 103.693,94.168 103.693,94.676 ; 103.693,94.168 104.201,94.168 ; 103.693,94.676 103.693,95.184 ; 103.693,94.676 104.201,94.676 ; 103.693,95.184 103.693,95.692 ; 103.693,95.184 104.201,95.184 ; 103.693,95.692 103.693,95.946 ; 103.693,95.692 104.201,95.692 ; 103.693,95.946 104.201,95.946 ; 104.182,86.548 104.201,86.567 ; 104.201,86.567 104.69,87.056 ; 104.201,86.567 104.201,87.056 ; 104.201,87.056 104.201,87.564 ; 104.201,87.056 104.69,87.056 ; 104.201,87.564 104.201,88.072 ; 104.201,87.564 104.709,87.564 ; 104.201,88.072 104.201,88.58 ; 104.201,88.072 104.709,88.072 ; 104.201,88.58 104.201,89.088 ; 104.201,88.58 104.709,88.58 ; 104.201,89.088 104.201,89.596 ; 104.201,89.088 104.709,89.088 ; 104.201,89.596 104.201,90.104 ; 104.201,89.596 104.709,89.596 ; 104.201,90.104 104.201,90.612 ; 104.201,90.104 104.709,90.104 ; 104.201,90.612 104.201,91.12 ; 104.201,90.612 104.709,90.612 ; 104.201,91.12 104.201,91.628 ; 104.201,91.12 104.709,91.12 ; 104.201,91.628 104.201,92.136 ; 104.201,91.628 104.709,91.628 ; 104.201,92.136 104.201,92.644 ; 104.201,92.136 104.709,92.136 ; 104.201,92.644 104.201,93.152 ; 104.201,92.644 104.709,92.644 ; 104.201,93.152 104.201,93.66 ; 104.201,93.152 104.709,93.152 ; 104.201,93.66 104.201,94.168 ; 104.201,93.66 104.709,93.66 ; 104.201,94.168 104.201,94.676 ; 104.201,94.168 104.709,94.168 ; 104.201,94.676 104.201,95.184 ; 104.201,94.676 104.709,94.676 ; 104.201,95.184 104.201,95.692 ; 104.201,95.184 104.709,95.184 ; 104.201,95.692 104.201,95.946 ; 104.201,95.692 104.709,95.692 ; 104.201,95.946 104.709,95.946 ; 104.69,87.056 104.709,87.075 ; 104.709,87.075 104.709,87.564 ; 104.709,87.075 105.198,87.564 ; 104.709,87.564 104.709,88.072 ; 104.709,87.564 105.198,87.564 ; 104.709,88.072 104.709,88.58 ; 104.709,88.072 105.217,88.072 ; 104.709,88.58 104.709,89.088 ; 104.709,88.58 105.217,88.58 ; 104.709,89.088 104.709,89.596 ; 104.709,89.088 105.217,89.088 ; 104.709,89.596 104.709,90.104 ; 104.709,89.596 105.217,89.596 ; 104.709,90.104 104.709,90.612 ; 104.709,90.104 105.217,90.104 ; 104.709,90.612 104.709,91.12 ; 104.709,90.612 105.217,90.612 ; 104.709,91.12 104.709,91.628 ; 104.709,91.12 105.217,91.12 ; 104.709,91.628 104.709,92.136 ; 104.709,91.628 105.217,91.628 ; 104.709,92.136 104.709,92.644 ; 104.709,92.136 105.217,92.136 ; 104.709,92.644 104.709,93.152 ; 104.709,92.644 105.217,92.644 ; 104.709,93.152 104.709,93.66 ; 104.709,93.152 105.217,93.152 ; 104.709,93.66 104.709,94.168 ; 104.709,93.66 105.217,93.66 ; 104.709,94.168 104.709,94.676 ; 104.709,94.168 105.217,94.168 ; 104.709,94.676 104.709,95.184 ; 104.709,94.676 105.217,94.676 ; 104.709,95.184 104.709,95.692 ; 104.709,95.184 105.217,95.184 ; 104.709,95.692 104.709,95.946 ; 104.709,95.692 pad.@105.217,95.692 ; 104.709,95.946 105.217,95.946 ; 105.198,87.564 105.217,87.583 ; 105.217,87.583 105.706,88.072 ; 105.217,87.583 105.217,88.072 ; 105.217,88.072 105.217,88.58 ; 105.217,88.072 105.706,88.072 ; 105.217,88.58 105.217,89.088 ; 105.217,88.58 105.725,88.58 ; 105.217,89.088 105.217,89.596 ; 105.217,89.088 105.725,89.088 ; 105.217,89.596 105.217,90.104 ; 105.217,89.596 105.725,89.596 ; 105.217,90.104 105.217,90.612 ; 105.217,90.104 105.725,90.104 ; 105.217,90.612 105.217,91.12 ; 105.217,90.612 105.725,90.612 ; 105.217,91.12 105.725,91.12 ; 105.217,91.12 105.217,91.628 ; 105.217,91.628 105.217,92.136 ; 105.217,91.628 105.498,91.628 ; 105.217,92.136 105.217,92.644 ; 105.217,92.136 105.467,92.136 ccw(c106.858,91.966) 105.498,91.628 ; 105.217,92.644 105.217,93.152 ; 105.217,92.644 105.631,92.644 ; 105.217,93.152 105.217,93.66 ; 105.217,93.152 105.725,93.152 ; 105.217,93.66 105.217,94.168 ; 105.217,93.66 105.725,93.66 ; 105.217,94.168 105.217,94.676 ; 105.217,94.168 105.725,94.168 ; 105.217,94.676 105.217,95.184 ; 105.217,94.676 105.725,94.676 ; 105.217,95.184 pad.@105.217,95.565 pad.@105.217,95.692 ; 105.217,95.184 105.725,95.184 ; pad.@105.217,95.692 105.217,95.946 ; pad.@105.217,95.692 105.725,95.692 ; 105.217,95.946 105.725,95.946 ; 105.706,88.072 105.725,88.091 ; 105.725,88.091 105.725,88.58 ; 105.725,88.091 106.214,88.58 ; 105.725,88.58 105.725,89.088 ; 105.725,88.58 106.214,88.58 ; 105.725,89.088 105.725,89.596 ; 105.725,89.088 106.233,89.088 ; 105.725,89.596 105.725,90.104 ; 105.725,89.596 106.233,89.596 ; 105.725,90.104 105.725,90.612 ; 105.725,90.104 pad.@106.233,90.104 ; 105.725,90.612 105.725,91.12 ; 105.725,90.612 106.233,90.612 ; 105.725,91.12 105.741,91.12 ; 105.725,91.12 105.725,91.142 ccw(c106.858,91.966) 105.741,91.12 ; 105.725,93.152 105.725,93.66 ; 105.725,93.152 105.725,92.791 cw(c106.858,91.966) 106.111,93.152 ; 105.725,93.152 106.111,93.152 ; 105.725,93.66 105.725,94.168 ; 105.725,93.66 106.233,93.66 ; 105.725,94.168 105.725,94.676 ; 105.725,94.168 106.233,94.168 ; 105.725,94.676 105.725,95.184 ; 105.725,94.676 106.233,94.676 ; 105.725,95.184 105.725,95.692 ; 105.725,95.184 106.233,95.184 ; 105.725,95.692 106.233,95.692 ; 105.725,95.692 105.725,95.946 ; 105.725,95.946 106.233,95.946 ; 106.111,93.152 cw(c106.858,91.966) 106.233,93.221 ; 106.214,88.58 106.233,88.599 ; 106.233,88.599 106.722,89.088 ; 106.233,88.599 106.233,89.088 ; 106.233,89.088 106.233,89.596 ; 106.233,89.088 106.722,89.088 ; 106.233,89.596 pad.@106.233,90.104 ; 106.233,89.596 106.741,89.596 ; pad.@106.233,90.104 106.233,90.612 ; pad.@106.233,90.104 106.741,90.104 ; 106.233,90.612 106.498,90.612 ; 106.233,93.221 cw(c106.858,91.966) 106.736,93.363 cw(c106.858,91.966) 106.741,93.363 ; 106.233,93.221 106.233,93.66 ; 106.233,93.66 106.233,94.168 ; 106.233,93.66 106.741,93.66 ; 106.233,94.168 106.233,94.676 ; 106.233,94.168 106.741,94.168 ; 106.233,94.676 106.233,95.184 ; 106.233,94.676 106.741,94.676 ; 106.233,95.184 106.233,95.692 ; 106.233,95.184 106.741,95.184 ; 106.233,95.692 106.741,95.692 ; 106.233,95.692 106.233,95.946 ; 106.233,95.946 106.741,95.946 ; 106.498,90.612 ccw(c106.858,91.966) 106.741,90.57 ; 106.722,89.088 106.741,89.107 ; 106.741,89.107 106.741,89.596 ; 106.741,89.107 106.776,89.142 106.776,89.596 ; 106.741,89.596 106.776,89.596 ; 106.741,89.596 106.741,90.104 ; 106.741,90.104 106.776,90.104 ; 106.741,90.104 106.741,90.57 ; 106.741,93.363 cw(c106.858,91.966) 107.245,93.314 cw(c106.858,91.966) 107.249,93.313 ; 106.741,93.363 106.741,93.66 ; 106.741,93.66 106.741,94.168 ; 106.741,93.66 107.249,93.66 ; 106.741,94.168 106.741,94.676 ; 106.741,94.168 107.249,94.168 ; 106.741,94.676 106.741,95.184 ; 106.741,94.676 107.249,94.676 ; 106.741,95.184 106.741,95.692 ; 106.741,95.184 107.249,95.184 ; 106.741,95.692 106.741,95.946 ; 106.741,95.692 107.249,95.692 ; 106.741,95.946 107.249,95.946 ; 106.776,89.596 106.776,90.104 ; 107.249,93.313 cw(c106.858,91.966) 107.606,93.152 ; 107.249,93.313 107.249,93.66 ; 107.249,93.66 107.249,94.168 ; 107.249,93.66 107.757,93.66 ; 107.249,94.168 107.249,94.676 ; 107.249,94.168 107.757,94.168 ; 107.249,94.676 107.249,95.184 ; 107.249,94.676 107.757,94.676 ; 107.249,95.184 107.249,95.692 ; 107.249,95.184 107.757,95.184 ; 107.249,95.692 107.249,95.946 ; 107.249,95.692 107.757,95.692 ; 107.249,95.946 107.757,95.946 ; 107.606,93.152 cw(c106.858,91.966) 107.757,93.042 ; 107.606,93.152 107.757,93.152 ; 107.757,93.042 107.757,93.152 ; 107.757,93.152 107.757,93.66 ; 107.757,93.152 107.867,93.152 ; 107.757,93.66 107.757,94.168 ; 107.757,93.66 107.897,93.66 ; 107.757,94.168 107.757,94.676 ; 107.757,94.168 108.138,94.168 ; 107.757,94.676 107.757,95.184 ; 107.757,94.676 108.265,94.676 ; 107.757,95.184 107.757,95.692 ; 107.757,95.184 108.265,95.184 ; 107.757,95.692 107.757,95.946 ; 107.757,95.692 108.265,95.692 ; 107.757,95.946 108.265,95.946 ; 107.867,93.152 cw(c109.258,93.325) 107.857,93.325 cw(c109.258,93.325) 107.897,93.66 ; 107.897,93.66 cw(c109.258,93.325) 107.898,93.664 cw(c109.258,93.325) 108.138,94.168 ; 108.138,94.168 cw(c109.258,93.325) 108.265,94.314 ; 108.219,91.628 ccw(c106.858,91.966) 108.26,91.966 ccw(c106.858,91.966) 108.25,92.136 ; 108.219,91.628 108.265,91.628 ; 108.25,92.136 108.265,92.136 ; 108.265,91.237 cw(c107.777,90.362) 108.432,91.12 ; 108.265,91.237 108.265,91.628 ; 108.265,91.628 108.265,92.136 ; 108.265,91.628 108.773,91.628 ; 108.265,92.136 108.516,92.136 ; 108.265,92.136 108.265,92.336 ; 108.265,92.336 ccw(c109.258,93.325) 108.516,92.136 ; 108.265,94.314 cw(c109.258,93.325) 108.267,94.316 cw(c109.258,93.325) 108.773,94.64 ; 108.265,94.314 108.265,94.676 ; 108.265,94.676 108.773,94.676 ; 108.265,94.676 108.265,95.184 ; 108.265,95.184 108.265,95.692 ; 108.265,95.184 108.773,95.184 ; 108.265,95.692 108.265,95.946 ; 108.265,95.692 108.773,95.692 ; 108.265,95.946 108.773,95.946 ; 108.432,91.12 cw(c107.777,90.362) 108.434,91.118 cw(c107.777,90.362) 108.747,90.612 ; 108.432,91.12 108.773,91.12 ; 108.516,92.136 ccw(c109.258,93.325) 108.773,92.01 ; 108.747,90.612 cw(c107.777,90.362) 108.773,90.471 ; 108.747,90.612 108.773,90.612 ; 108.773,90.471 cw(c107.777,90.362) 108.779,90.362 108.779,90.104 ; 108.773,90.471 108.773,90.612 ; 108.773,90.612 108.773,91.12 ; 108.773,90.612 109.281,90.612 ; 108.773,91.12 108.773,91.628 ; 108.773,91.12 109.281,91.12 ; 108.773,91.628 109.281,91.628 ; 108.773,91.628 108.773,92.01 ; 108.773,92.01 ccw(c109.258,93.325) 109.281,91.924 ; 108.773,94.64 cw(c109.258,93.325) 108.779,94.642 cw(c109.258,93.325) 108.885,94.676 ; 108.773,94.64 108.773,94.676 ; 108.773,94.676 108.773,95.184 ; 108.773,94.676 108.885,94.676 ; 108.773,95.184 108.773,95.692 ; 108.773,95.184 109.281,95.184 ; 108.773,95.692 108.773,95.946 ; 108.773,95.692 109.281,95.692 ; 108.773,95.946 109.281,95.946 ; 108.779,90.104 109.281,90.104 ; 108.779,90.104 108.779,89.536 109.281,90.038 ; 108.885,94.676 cw(c109.258,93.325) 109.281,94.726 ; 109.281,90.038 109.789,90.546 ; 109.281,90.038 109.281,90.104 ; 109.281,90.104 109.281,90.612 ; 109.281,90.612 109.789,90.612 ; 109.281,90.612 109.281,91.12 ; 109.281,91.12 109.281,91.628 ; 109.281,91.12 109.789,91.12 ; 109.281,91.628 109.789,91.628 ; 109.281,91.628 109.281,91.924 ; 109.281,91.924 ccw(c109.258,93.325) 109.283,91.924 ccw(c109.258,93.325) 109.789,92.028 ; 109.281,94.726 cw(c109.258,93.325) 109.283,94.726 cw(c109.258,93.325) 109.631,94.676 ; 109.281,94.726 109.281,95.184 ; 109.281,95.184 109.281,95.692 ; 109.281,95.184 109.789,95.184 ; 109.281,95.692 109.281,95.946 ; 109.281,95.692 109.789,95.692 ; 109.281,95.946 109.789,95.946 ; 109.631,94.676 cw(c109.258,93.325) 109.783,94.625 cw(c109.258,93.325) 109.789,94.622 ; 109.631,94.676 109.789,94.676 ; 109.789,90.546 109.855,90.612 ; 109.789,90.546 109.789,90.612 ; 109.789,90.612 109.789,91.12 ; 109.789,90.612 109.855,90.612 ; 109.789,91.12 110.297,91.12 ; 109.789,91.12 109.789,91.628 ; 109.789,91.628 110.297,91.628 ; 109.789,91.628 109.789,92.028 ; 109.789,92.028 ccw(c109.258,93.325) 110,92.136 ; 109.789,94.622 cw(c109.258,93.325) 110.297,94.266 ; 109.789,94.622 109.789,94.676 ; 109.789,94.676 110.297,94.676 ; 109.789,94.676 109.789,95.184 ; 109.789,95.184 109.789,95.692 ; 109.789,95.184 110.297,95.184 ; 109.789,95.692 109.789,95.946 ; 109.789,95.692 110.297,95.692 ; 109.789,95.946 110.297,95.946 ; 109.855,90.612 110.297,91.054 ; 110,92.136 ccw(c109.258,93.325) 110.297,92.384 ; 110,92.136 110.297,92.136 ; 110.297,91.054 110.297,91.12 ; 110.297,91.054 110.363,91.12 ; 110.297,91.12 110.297,91.628 ; 110.297,91.12 110.363,91.12 ; 110.297,91.628 110.805,91.628 ; 110.297,91.628 110.297,92.136 ; 110.297,92.136 110.805,92.136 ; 110.297,92.136 110.297,92.384 ; 110.297,92.384 ccw(c109.258,93.325) 110.3,92.387 ccw(c109.258,93.325) 110.483,92.644 ; 110.297,94.266 110.297,94.676 ; 110.297,94.676 110.297,95.184 ; 110.297,94.676 110.805,94.676 ; 110.297,95.184 110.297,95.692 ; 110.297,95.184 110.805,95.184 ; 110.297,95.692 110.297,95.946 ; 110.297,95.692 110.805,95.692 ; 110.297,95.946 110.805,95.946 ; 110.363,91.12 110.805,91.562 ; 110.483,92.644 ccw(c109.258,93.325) 110.484,92.645 ccw(c109.258,93.325) 110.66,93.325 ccw(c109.258,93.325) 110.619,93.66 ; 110.483,92.644 110.805,92.644 ; 110.619,93.66 ccw(c109.258,93.325) 110.618,93.664 ccw(c109.258,93.325) 110.378,94.168 110.805,94.168 ; 110.619,93.66 110.697,93.66 ; 110.805,91.562 110.805,91.628 ; 110.805,91.562 110.871,91.628 ; 110.805,91.628 110.805,92.136 ; 110.805,91.628 110.871,91.628 ; 110.805,92.136 110.805,92.644 ; 110.805,92.136 111.183,92.136 ; 110.805,92.644 110.899,92.644 ; 110.805,92.644 110.805,92.813 ccw(c112.075,93.406) 110.899,92.644 ; 110.805,94.168 110.805,94.676 ; 110.805,94.168 110.805,93.999 cw(c112.075,93.406) 110.899,94.168 ; 110.805,94.168 110.899,94.168 ; 110.805,94.676 111.313,94.676 ; 110.805,94.676 110.805,95.184 ; 110.805,95.184 110.805,95.692 ; 110.805,95.184 111.313,95.184 ; 110.805,95.692 110.805,95.946 ; 110.805,95.692 111.313,95.692 ; 110.805,95.946 111.313,95.946 ; 110.871,91.628 111.183,91.941 111.183,92.136 ; 111.313,94.676 111.313,95.184 ; 111.313,94.676 111.482,94.676 ; 111.313,95.184 pad.@111.821,95.184 ; 111.313,95.184 111.313,95.692 ; 111.313,95.692 111.313,95.946 ; 111.313,95.692 pad.@111.821,95.692 ; 111.313,95.946 111.821,95.946 ; 111.482,94.676 cw(c112.075,93.406) 111.821,94.784 ; 111.821,94.784 pad.@111.821,95.184 ; pad.@111.821,95.184 112.329,95.184 ; pad.@111.821,95.184 pad.@111.821,95.692 ; pad.@111.821,95.692 111.821,95.946 ; pad.@111.821,95.692 112.329,95.692 ; 111.821,95.946 112.329,95.946 ; 112.329,95.184 112.329,95.692 ; 112.329,95.184 112.837,95.184 ; 112.329,95.692 112.329,95.946 ; 112.329,95.692 112.837,95.692 ; 112.329,95.946 112.837,95.946 ; 112.668,94.676 cw(c112.075,93.406) 112.837,94.582 ; 112.668,94.676 112.837,94.676 ; 112.837,62.799 pad.@112.837,63.166 ; 112.837,62.799 112.47,62.799 pad.@112.837,63.166 ; 112.837,62.799 113.307,62.799 ; pad.@112.837,63.166 pad.@112.851,63.18 ; 112.837,94.582 cw(c112.075,93.406) 112.838,94.581 cw(c112.075,93.406) 113.251,94.168 ; 112.837,94.582 112.837,94.676 ; 112.837,94.676 113.345,94.676 ; 112.837,94.676 112.837,95.184 ; 112.837,95.184 112.837,95.692 ; 112.837,95.184 113.345,95.184 ; 112.837,95.692 112.837,95.946 ; 112.837,95.692 113.345,95.692 ; 112.837,95.946 113.345,95.946 ; pad.@112.851,63.18 113.139,63.467 113.345,63.467 ; pad.@112.851,63.18 pad.@113.345,63.18 ; 113.251,92.644 ccw(c112.075,93.406) 113.345,92.813 ; 113.251,92.644 113.345,92.644 ; 113.251,94.168 cw(c112.075,93.406) 113.345,93.999 113.345,94.168 ; 113.251,94.168 113.345,94.168 ; 113.307,62.799 ccw(c113.917,61.593) 113.303,62.797 cw(c113.917,61.593) 113.307,62.799 ; 113.307,62.799 cw(c113.917,61.593) 113.345,62.817 ; 113.307,62.799 cw(c113.917,61.593) 113.345,62.817 ; 113.345,62.817 cw(c113.917,61.593) 113.853,62.943 ; 113.345,62.817 cw(c113.917,61.593) 113.853,62.943 ; 113.345,62.817 pad.@113.345,63.18 ; pad.@113.345,63.18 113.853,63.18 ; pad.@113.345,63.18 113.345,63.467 ; 113.345,63.467 113.853,63.467 ; 113.345,92.642 113.345,92.644 ; 113.345,92.642 113.853,92.642 ; 113.345,92.644 113.853,92.644 ; 113.345,92.644 113.345,92.813 ; 113.345,92.813 ccw(c112.075,93.406) 113.453,93.152 ; 113.345,94.168 113.345,94.676 ; 113.345,94.168 113.853,94.168 ; 113.345,94.676 113.345,95.184 ; 113.345,94.676 113.853,94.676 ; 113.345,95.184 113.345,95.692 ; 113.345,95.184 113.853,95.184 ; 113.345,95.692 113.853,95.692 ; 113.345,95.692 113.345,95.946 ; 113.345,95.946 113.853,95.946 ; 113.453,93.152 ccw(c112.075,93.406) 113.455,93.163 ccw(c112.075,93.406) 113.453,93.66 ; 113.453,93.152 113.853,93.152 ; 113.453,93.66 113.853,93.66 ; 113.668,70.357 cw(c113.576,69.379) 113.853,70.322 ; 113.668,70.357 113.668,70.8 ; 113.668,70.8 113.853,70.8 ; 113.668,70.8 113.668,71.308 ; 113.668,71.308 113.853,71.308 ; 113.668,71.308 113.668,71.816 ; 113.668,71.816 113.853,71.816 ; 113.668,71.816 113.668,72.324 ; 113.668,72.324 113.853,72.324 ; 113.668,72.324 113.668,72.832 ; 113.668,72.832 113.853,72.832 ; 113.668,72.832 113.668,73.34 ; 113.668,73.34 113.853,73.34 ; 113.668,73.34 113.668,73.848 ; 113.668,73.848 113.853,73.848 ; 113.668,73.848 113.668,74.356 ; 113.668,74.356 113.853,74.356 ; 113.668,74.356 113.668,74.864 ; 113.668,74.864 113.853,74.864 ; 113.668,74.864 113.668,75.372 ; 113.668,75.372 113.853,75.372 ; 113.668,75.372 113.668,75.88 ; 113.668,75.88 113.853,75.88 ; 113.668,75.88 113.668,76.388 ; 113.668,76.388 113.853,76.388 ; 113.668,76.388 113.668,76.896 ; 113.668,76.896 113.668,77.404 ; 113.668,76.896 113.853,76.896 ; 113.668,77.404 113.853,77.404 ; 113.668,77.404 113.668,77.912 ; 113.668,77.912 113.853,77.912 ; 113.668,77.912 113.668,78.42 ; 113.668,78.42 113.853,78.42 ; 113.668,78.42 113.668,78.928 ; 113.668,78.928 113.853,78.928 ; 113.668,78.928 113.668,79.436 ; 113.668,79.436 113.853,79.436 ; 113.668,79.436 113.668,79.944 ; 113.668,79.944 113.853,79.944 ; 113.668,79.944 113.668,80.198 113.853,80.198 ; 113.853,62.943 cw(c113.917,61.593) 113.917,62.944 ; 113.853,62.943 cw(c113.917,61.593) 113.917,62.944 ; 113.853,62.943 113.853,63.18 ; 113.853,63.18 113.853,63.467 ; 113.853,63.18 pad.@114.361,63.18 ; 113.853,63.467 pad.@114.361,63.467 ; 113.853,70.322 cw(c113.576,69.379) 113.94,70.292 ; 113.853,70.322 113.853,70.8 ; 113.853,70.8 113.853,71.308 ; 113.853,70.8 114.361,70.8 ; 113.853,71.308 113.853,71.816 ; 113.853,71.308 114.361,71.308 ; 113.853,71.816 113.853,72.324 ; 113.853,71.816 114.361,71.816 ; 113.853,72.324 113.853,72.832 ; 113.853,72.324 114.361,72.324 ; 113.853,72.832 113.853,73.34 ; 113.853,72.832 114.361,72.832 ; 113.853,73.34 113.853,73.848 ; 113.853,73.34 114.361,73.34 ; 113.853,73.848 113.853,74.356 ; 113.853,73.848 114.361,73.848 ; 113.853,74.356 113.853,74.864 ; 113.853,74.356 114.361,74.356 ; 113.853,74.864 113.853,75.372 ; 113.853,74.864 114.361,74.864 ; 113.853,75.372 113.853,75.88 ; 113.853,75.372 114.361,75.372 ; 113.853,75.88 113.853,76.388 ; 113.853,75.88 114.361,75.88 ; 113.853,76.388 113.853,76.896 ; 113.853,76.388 114.361,76.388 ; 113.853,76.896 113.853,77.404 ; 113.853,76.896 114.361,76.896 ; 113.853,77.404 114.361,77.404 ; 113.853,77.404 113.853,77.912 ; 113.853,77.912 114.361,77.912 ; 113.853,77.912 113.853,78.42 ; 113.853,78.42 114.361,78.42 ; 113.853,78.42 113.853,78.928 ; 113.853,78.928 113.853,79.436 ; 113.853,78.928 114.361,78.928 ; 113.853,79.436 113.853,79.944 ; 113.853,79.436 114.361,79.436 ; 113.853,79.944 113.853,80.198 ; 113.853,79.944 114.361,79.944 ; 113.853,80.198 114.361,80.198 ; 113.853,92.642 113.853,92.644 ; 113.853,92.642 113.873,92.642 ; 113.853,92.644 113.853,93.152 ; 113.853,92.644 113.876,92.644 ; 113.853,93.152 113.853,93.66 ; 113.853,93.152 114.361,93.152 ; 113.853,93.66 113.853,94.168 ; 113.853,93.66 114.361,93.66 ; 113.853,94.168 113.853,94.676 ; 113.853,94.168 114.361,94.168 ; 113.853,94.676 113.853,95.184 ; 113.853,94.676 114.361,94.676 ; 113.853,95.184 113.853,95.692 ; 113.853,95.184 114.361,95.184 ; 113.853,95.692 114.361,95.692 ; 113.853,95.692 113.853,95.946 ; 113.853,95.946 114.361,95.946 ; 113.873,92.642 cw(c114.506,91.891) 113.876,92.644 ; 113.917,62.944 pad.@114.361,62.944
